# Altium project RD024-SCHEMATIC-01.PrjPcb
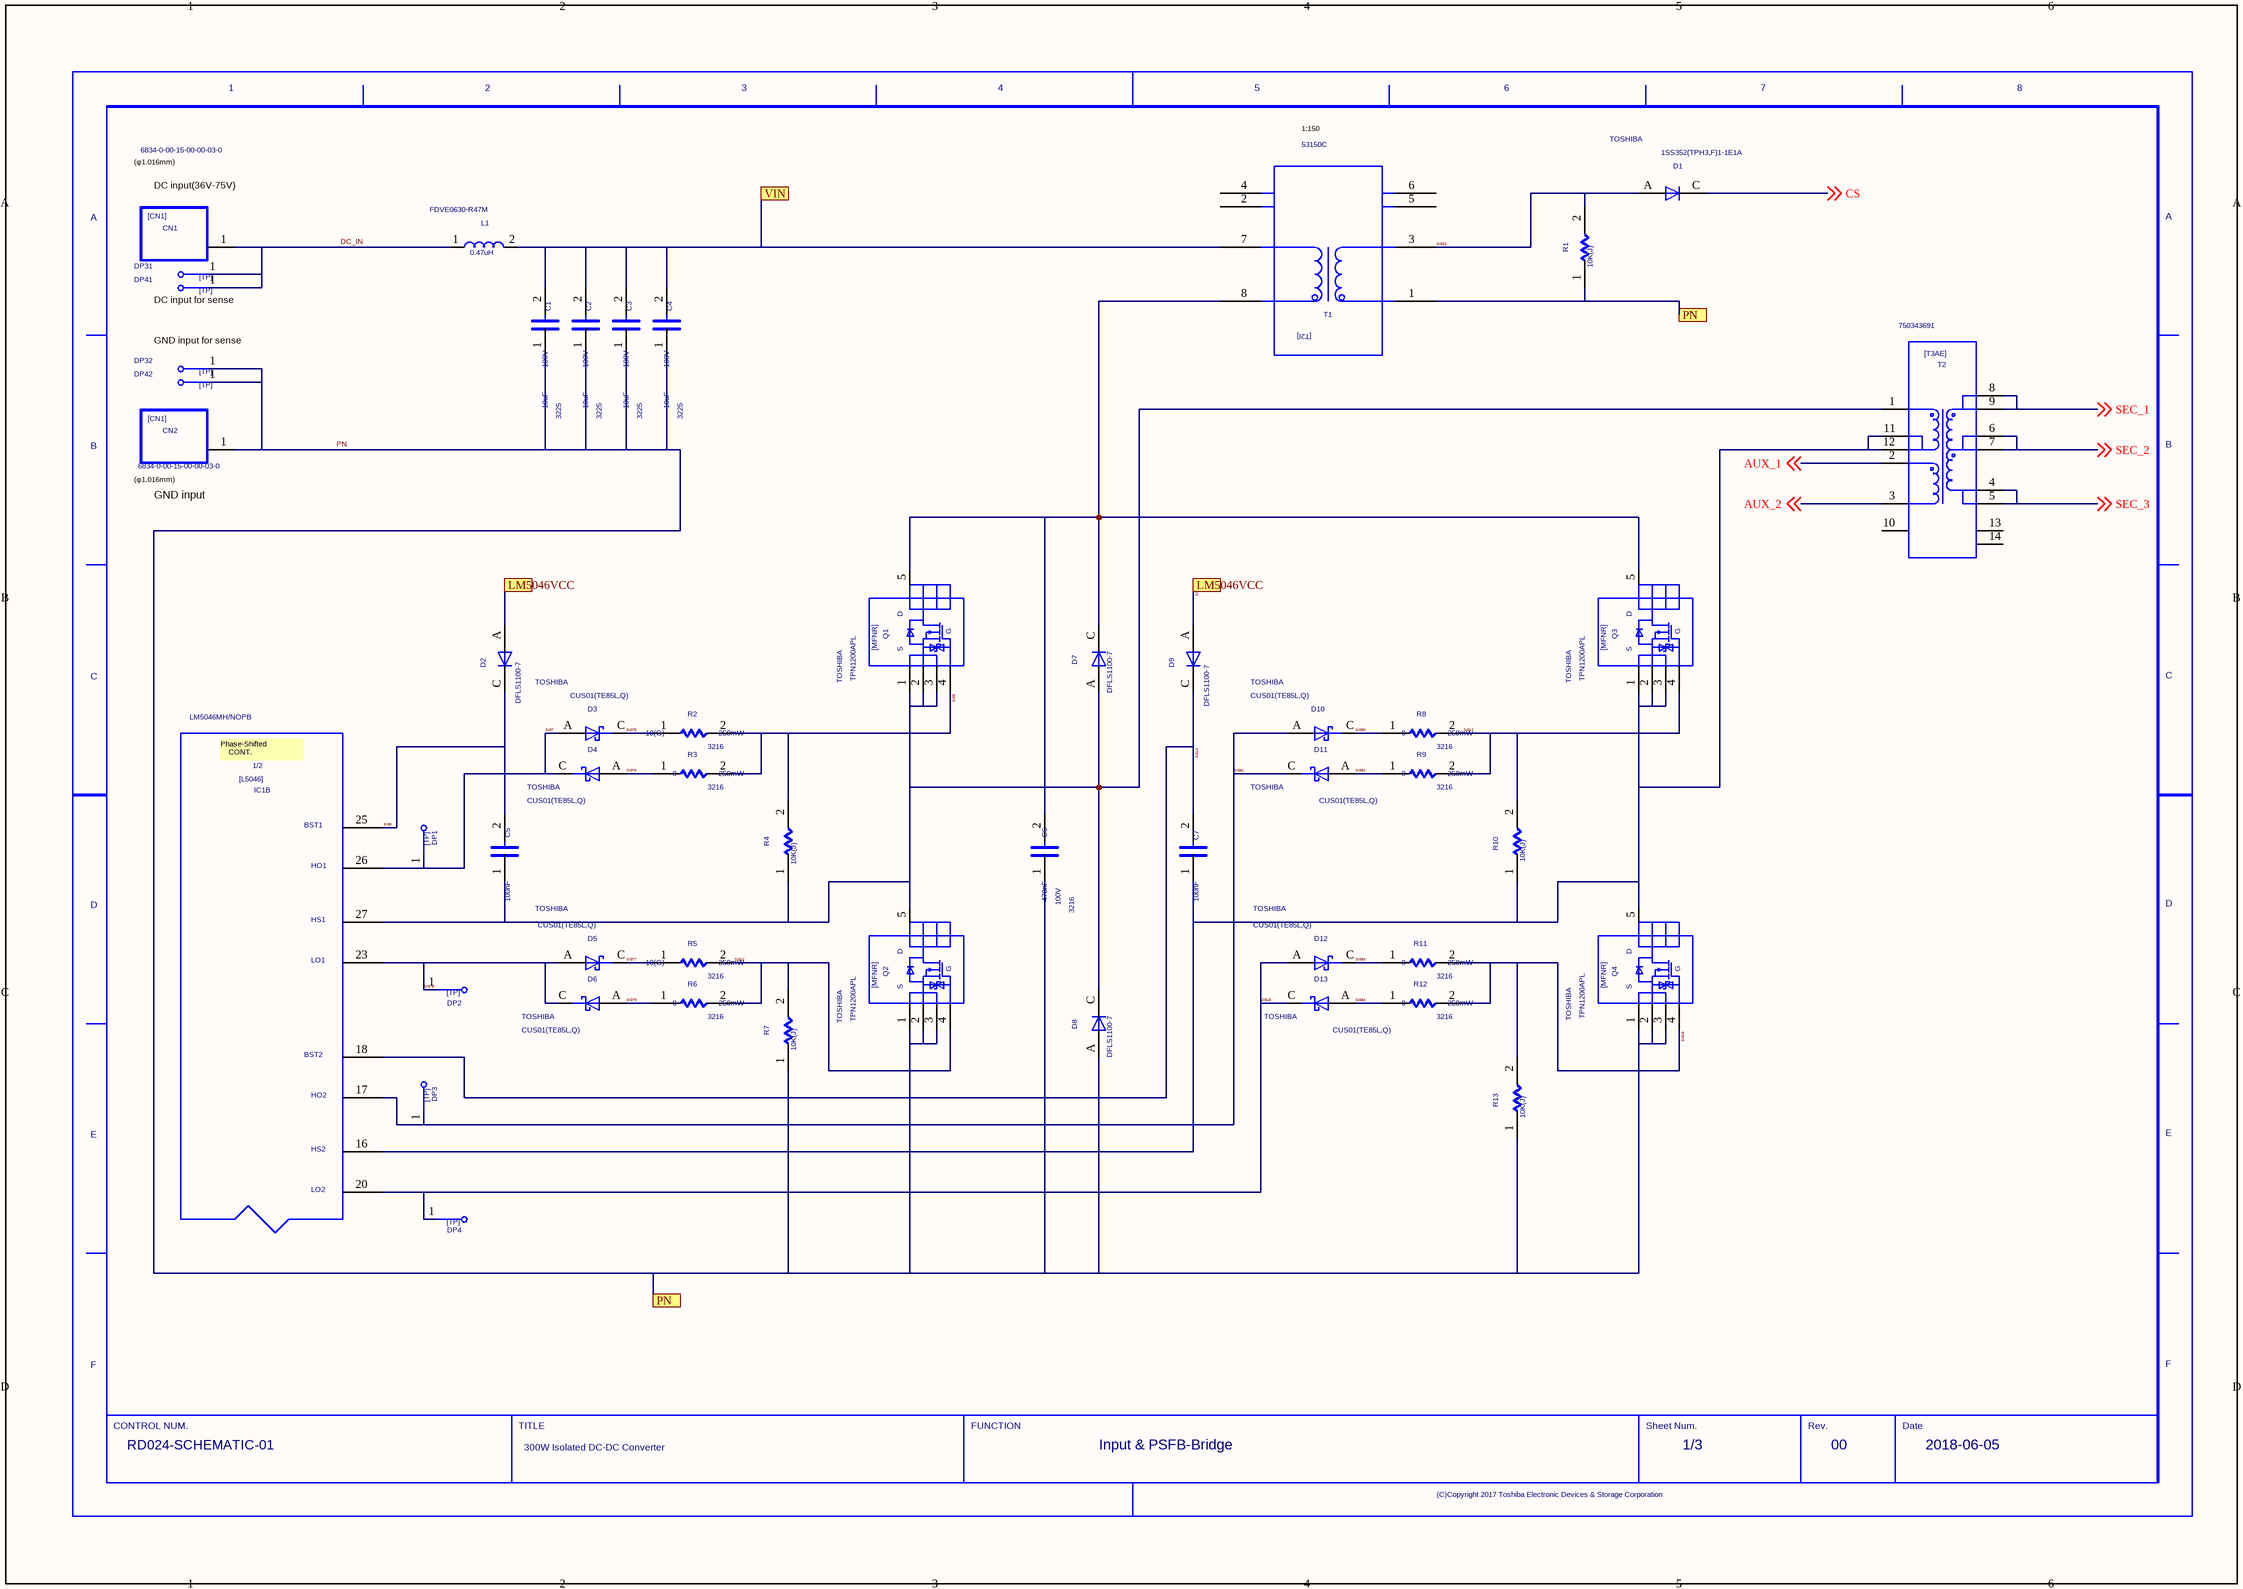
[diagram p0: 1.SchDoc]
3 sheets, 229 parts. Net scope: flat (ports and power ports of the same name join across sheets).
Sheets:
  1.SchDoc
  2.SchDoc
  3.SchDoc

## Sheet 1.SchDoc
size 420 x 297 mm

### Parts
(Parts that share a designator on the sheet are numbered #1, #2 ... from top to bottom, then left to right.)
C1  10uF  VALUE2: 100V  SIZECODESMD: 3225
C2  10uF  VALUE2: 100V  SIZECODESMD: 3225
C3  10uF  VALUE2: 100V  SIZECODESMD: 3225
C4  10uF  VALUE2: 100V  SIZECODESMD: 3225
C5  100nF
C6  470nF  VALUE2: 100V  COMPCOMMENT: 3216
C7  100nF
CN1  VALUE3: 6834-0-00-15-00-00-03-0  (hidden comment: CN1)
CN2  VALUE3: 6834-0-00-15-00-00-03-0  (hidden comment: CN1)
D1  1SS352(TPH3,F)1-1E1A  USERCOMPTEXT3: TOSHIBA
D2  VALUE3: DFLS1100-7  (hidden comment: D)
D3  CUS01(TE85L,Q)  USERCOMPTEXT3: TOSHIBA
D4  USERCOMPTEXT3: TOSHIBA  (hidden comment: CUS01(TE85L,Q))
D5  USERCOMPTEXT3: TOSHIBA  (hidden comment: CUS01(TE85L,Q))
D6  USERCOMPTEXT3: TOSHIBA  (hidden comment: CUS01(TE85L,Q))
D7  VALUE3: DFLS1100-7  (hidden comment: D)
D8  VALUE3: DFLS1100-7  (hidden comment: D)
D9  VALUE3: DFLS1100-7  (hidden comment: D)
D10  USERCOMPTEXT3: TOSHIBA  (hidden comment: CUS01(TE85L,Q))
D11  USERCOMPTEXT3: TOSHIBA  (hidden comment: CUS01(TE85L,Q))
D12  USERCOMPTEXT3: TOSHIBA  (hidden comment: CUS01(TE85L,Q))
D13  USERCOMPTEXT3: TOSHIBA  (hidden comment: CUS01(TE85L,Q))
DP1  TP  (value not drawn)
DP2  TP  (value not drawn)
DP3  TP  (value not drawn)
DP4  TP  (value not drawn)
DP31  TP  (value not drawn)
DP32  TP  (value not drawn)
DP41  TP  (value not drawn)
DP42  TP  (value not drawn)
IC1  VALUE3: LM5046MH/NOPB  (hidden comment: L5046_1)  (part B of 2)
L1  0.47uH  VALUE3: FDVE0630-R47M
Q1  USERCOMPTEXT3: TOSHIBA  VALUE3: TPN1200APL  (hidden comment: MFNR)
Q2  USERCOMPTEXT3: TOSHIBA  VALUE3: TPN1200APL  (hidden comment: MFNR)
Q3  USERCOMPTEXT3: TOSHIBA  VALUE3: TPN1200APL  (hidden comment: MFNR)
Q4  USERCOMPTEXT3: TOSHIBA  VALUE3: TPN1200APL  (hidden comment: MFNR)
R1  10K(J)
R2  10(G)  SIZECODESMD: 3216  VALUE2: 250mW
R3  0  VALUE2: 250mW  COMPCOMMENT: 3216
R4  10K(J)
R5  10(G)  SIZECODESMD: 3216  VALUE2: 250mW
R6  0  VALUE2: 250mW  COMPCOMMENT: 3216
R7  10K(J)
R8  0  VALUE2: 250mW  COMPCOMMENT: 3216
R9  0  VALUE2: 250mW  COMPCOMMENT: 3216
R10  10K(J)
R11  0  VALUE2: 250mW  COMPCOMMENT: 3216
R12  0  VALUE2: 250mW  COMPCOMMENT: 3216
R13  10K(J)
T1  VALUE3: 53150C  (hidden comment: T2I)
T2  VALUE3: 750343691  (hidden comment: T3AE)
U?#1  DATE: 2018-06-05  FUNCTION: Input & PSFB-Bridge  DRAWINGNUMBER: RD024-SCHEMATIC-01  TITLE: 300W Isolated DC-DC Converter  REVISION: 00  SHEETNUMBER: 1/3  (hidden comment: WAKU_DEF100)

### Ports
LM5046VCC, PN, VIN

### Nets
AUX_1: T2.2 ; off-sheet AUX_1
AUX_2: T2.3 ; off-sheet AUX_2
CS: D1.C ; off-sheet CS
DC_IN: CN1.1 DP31.1 DP41.1 L1.1
PN: C1.1 C2.1 C3.1 C4.1 C6.1 CN2.1 D8.A DP32.1 DP42.1 Q2.1 Q2.2 Q2.3 Q4.1 Q4.2 Q4.3 R1.1 R7.1 R13.1 T1.1 ; port PN
SEC_1: T2.8 T2.9 ; off-sheet SEC_1
SEC_2: T2.6 T2.7 ; off-sheet SEC_2
SEC_3: T2.4 T2.5 ; off-sheet SEC_3
SIG7: D3.A D4.C DP1.1 IC1.26
SIG8: C5.2 D2.C IC1.25
SIG9: Q1.4 R2.2 R3.2 R4.2
SIG12: Q2.4 R5.2 R6.2 R7.2
SIG13: D2.A D9.A ; port LM5046VCC
SIG14: C7.2 D9.C IC1.18
SIG16: Q4.4 R11.2 R12.2 R13.2
SIG17: Q3.4 R8.2 R9.2 R10.2
SIG18: D12.A D13.C DP4.1 IC1.20
SIG22: C6.2 D7.C Q1.5 Q3.5 T1.8
SIG23: D1.A R1.2 T1.3
SIG75: D3.C R2.1
SIG76: D4.A R3.1
SIG77: D5.C R5.1
SIG78: D5.A D6.C DP2.1 IC1.23
SIG79: D6.A R6.1
SIG80: D10.C R8.1
SIG81: D10.A D11.C DP3.1 IC1.17
SIG82: D11.A R9.1
SIG83: D12.C R11.1
SIG84: D13.A R12.1
SIG145: C5.1 D7.A D8.C IC1.27 Q1.1 Q1.2 Q1.3 Q2.5 R4.1 T2.1
SIG148: C7.1 IC1.16 Q3.1 Q3.2 Q3.3 Q4.5 R10.1 T2.11 T2.12
NetC1_2: C1.2 C2.2 C3.2 C4.2 L1.2 T1.7 ; port VIN

Not connected (* = marked no-connect by the designer): T1 2 4 5 6; T2 10 13 14

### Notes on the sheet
- (φ1.016mm)
- DC input(36V-75V)
- 1:150
- (near DP41) DC input for sense
- GND input for sense
- (near CN2) (φ1.016mm)
- (near CN2) GND input

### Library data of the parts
C1-C4 = C: SQ_PART_MODEL: CON_100U; OriginalSymbolOrigin: (2540,7620); RATEDVOLTAGE: 4; MAXGCOUNT: 1; OUMEMAKER: MRT 村田製作所; OUMECLASSIFICATION: セラミックコンデンサ; COMP: PRT_2; NOMINALCAPACITA: 100u; ADSCNVFLAG: ON; OUMEMAKERKATAMEI: GRM32EC80G107ME20L; ADSCOMPONENTNAME: C_3225; VALUE3: GRM32EC72A106KE05#; CAPACITANCETOLE: M; CDMASTERCADCELG: DC903A; ADSMODELNAME: s_GRM32EC80G107ME20L
C5 C7 = C: SQ_PART_MODEL: CON_100N; OriginalSymbolOrigin: (2540,7620); RATEDVOLTAGE: 25; MAXGCOUNT: 1; OUMEMAKER: MRT 村田製作所; OUMECLASSIFICATION: セラミックコンデンサ; COMP: PRT_4; SIZECODESMD: 1005; NOMINALCAPACITA: 100n; ADSCNVFLAG: ON; OUMEMAKERKATAMEI: GRM155R71E104KE14D; ADSCOMPONENTNAME: C_1005; VALUE3: GRM155R71E104KE14#; VALUE2: 25V; CAPACITANCETOLE: K; CDMASTERCADCELG: KC0005; ADSMODELNAME: s_GRM155R71E104KE14D
C6 = C: OriginalSymbolOrigin: (2540,7620); VALUE3: GRM31MR72A474KA35#; COMP: PRT_13
CN1 CN2 = CN1: OriginalSymbolOrigin: (2540,12700); COMP: PRT_16
D1 = D: SAVEAREA0: -225,-91,12804,7836; SAVECOUNT: 3; TIME: 14:49:55; UPDATEUSER: 19870035; UPDATETIME: 14:20:16; OriginalSymbolOrigin: (5080,5080); MAXGCOUNT: 1; COMP: PRT_3
D2 D7-D9 = D: SAVEAREA0: -225,-91,12804,7836; SAVECOUNT: 3; TIME: 14:49:55; UPDATEUSER: 19870035; UPDATETIME: 14:20:16; OriginalSymbolOrigin: (5080,5080); COMP: PRT_9
D3-D6 D10-D13 = SBD: OUMEPARTTYPE: D; SAVEAREA0: -4630,-153,17114,13055; TIME: 14:49:55; UPDATEUSER: fukuda-y; UPDATETIME: 08:16:22; SAVECOUNT: 9; OriginalSymbolOrigin: (5080,5080); MAXGCOUNT: 1; COMP: PRT_7
DP1-DP4 DP31 DP32 DP41 DP42 = TP: TIME: 16:12:21; UPDATEUSER: fukuda-y; UPDATETIME: 16:18:11; SAVECOUNT: 2; SAVEAREA0: -242,-92,12810,7836; OriginalSymbolOrigin: (0,7620); MAXGCOUNT: 1; COMP: PRT_10
IC1 = L5046_1: SAVEAREA0: -71804,-1007,117827,97484; TIME: 14:38:41; UPDATEUSER: cae; UPDATETIME: 09:49:47; SAVECOUNT: 16; OriginalSymbolOrigin: (7620,93980); CaptureCellPackProp: L5046_1B; COMP: PRT_6
L1 = L: OriginalSymbolOrigin: (2540,5080); RATEDCURRENT: 3.3; INDUCTANCEMAX: 0; MAXGCOUNT: 1; OUMEMAKER: TKO 東光; MOUNTINGFORMSMD: SMD; OUMECLASSIFICATION: 表面実装用固定コイル; COMP: PRT_1; ADSCNVFLAG: ON; OUMEMAKERKATAMEI: FDV0630-4R7M=P3; ADSCOMPONENTNAME: L_SMD; CDMASTERCADCELG: KD0074; ADSMODELNAME: s_FDV0630_4R7M_P3; NOMINALINDUCTA2: M; NOMINALINDUCTA1: 4.7u
Q1-Q4 = MFNR: SAVEAREA0: -11373,-4619,33654,28142; TIME: 18:57:44; UPDATEUSER: ikeda-k; UPDATETIME: 16:18:19; SAVECOUNT: 11; OriginalSymbolOrigin: (5080,20320); COMP: PRT_15
R1 = R: OriginalSymbolOrigin: (5080,5080); VALUE2: 63mW; MAXGCOUNT: 1; COMP: PRT_8; SIZECODESMD: 1005; VALUE3: ERJ2GEJ103X
R2 R5 = R: OriginalSymbolOrigin: (5080,5080); MAXGCOUNT: 1; VALUE3: RK73B2BTTD100G; COMP: PRT_14
R3 R6 R8 R9 R11 R12 = R: OriginalSymbolOrigin: (5080,5080); VALUE3: RK73Z2BRTTD; COMP: PRT_12
R4 R7 R10 R13 = R: OriginalSymbolOrigin: (5080,5080); MAXGCOUNT: 1; COMP: PRT_8; SIZECODESMD: 1005; VALUE3: ERJ2GEJ103X; VALUE2: 63mW
T1 = T2I: SAVEAREA0: -21366,-459,62077,41078; SAVECOUNT: 8; TIME: 14:27:07; UPDATEUSER: 19990028; UPDATETIME: 13:00:08; OriginalSymbolOrigin: (7620,38100); COMP: PRT_11
T2 = T3AE: SAVEAREA0: -34674,-485,56770,47009; TIME: 17:49:49; UPDATEUSER: cae; UPDATETIME: 15:15:30; SAVECOUNT: 3; OriginalSymbolOrigin: (5080,43180); COMP: PRT_17
U?#1 = WAKU_DEF100: PLOTTIME: HH:MM; SAVEAREA0: -45080,-4508,463680,304612; TIME: 09:33:31; UPDATEUSER: d5009410; UPDATETIME: 14:09:13; SAVECOUNT: 3; OriginalSymbolOrigin: (10160,284480); PAGENUMBER: 01; DESIGNED: TOSHIBA

## Sheet 2.SchDoc
size 420 x 297 mm
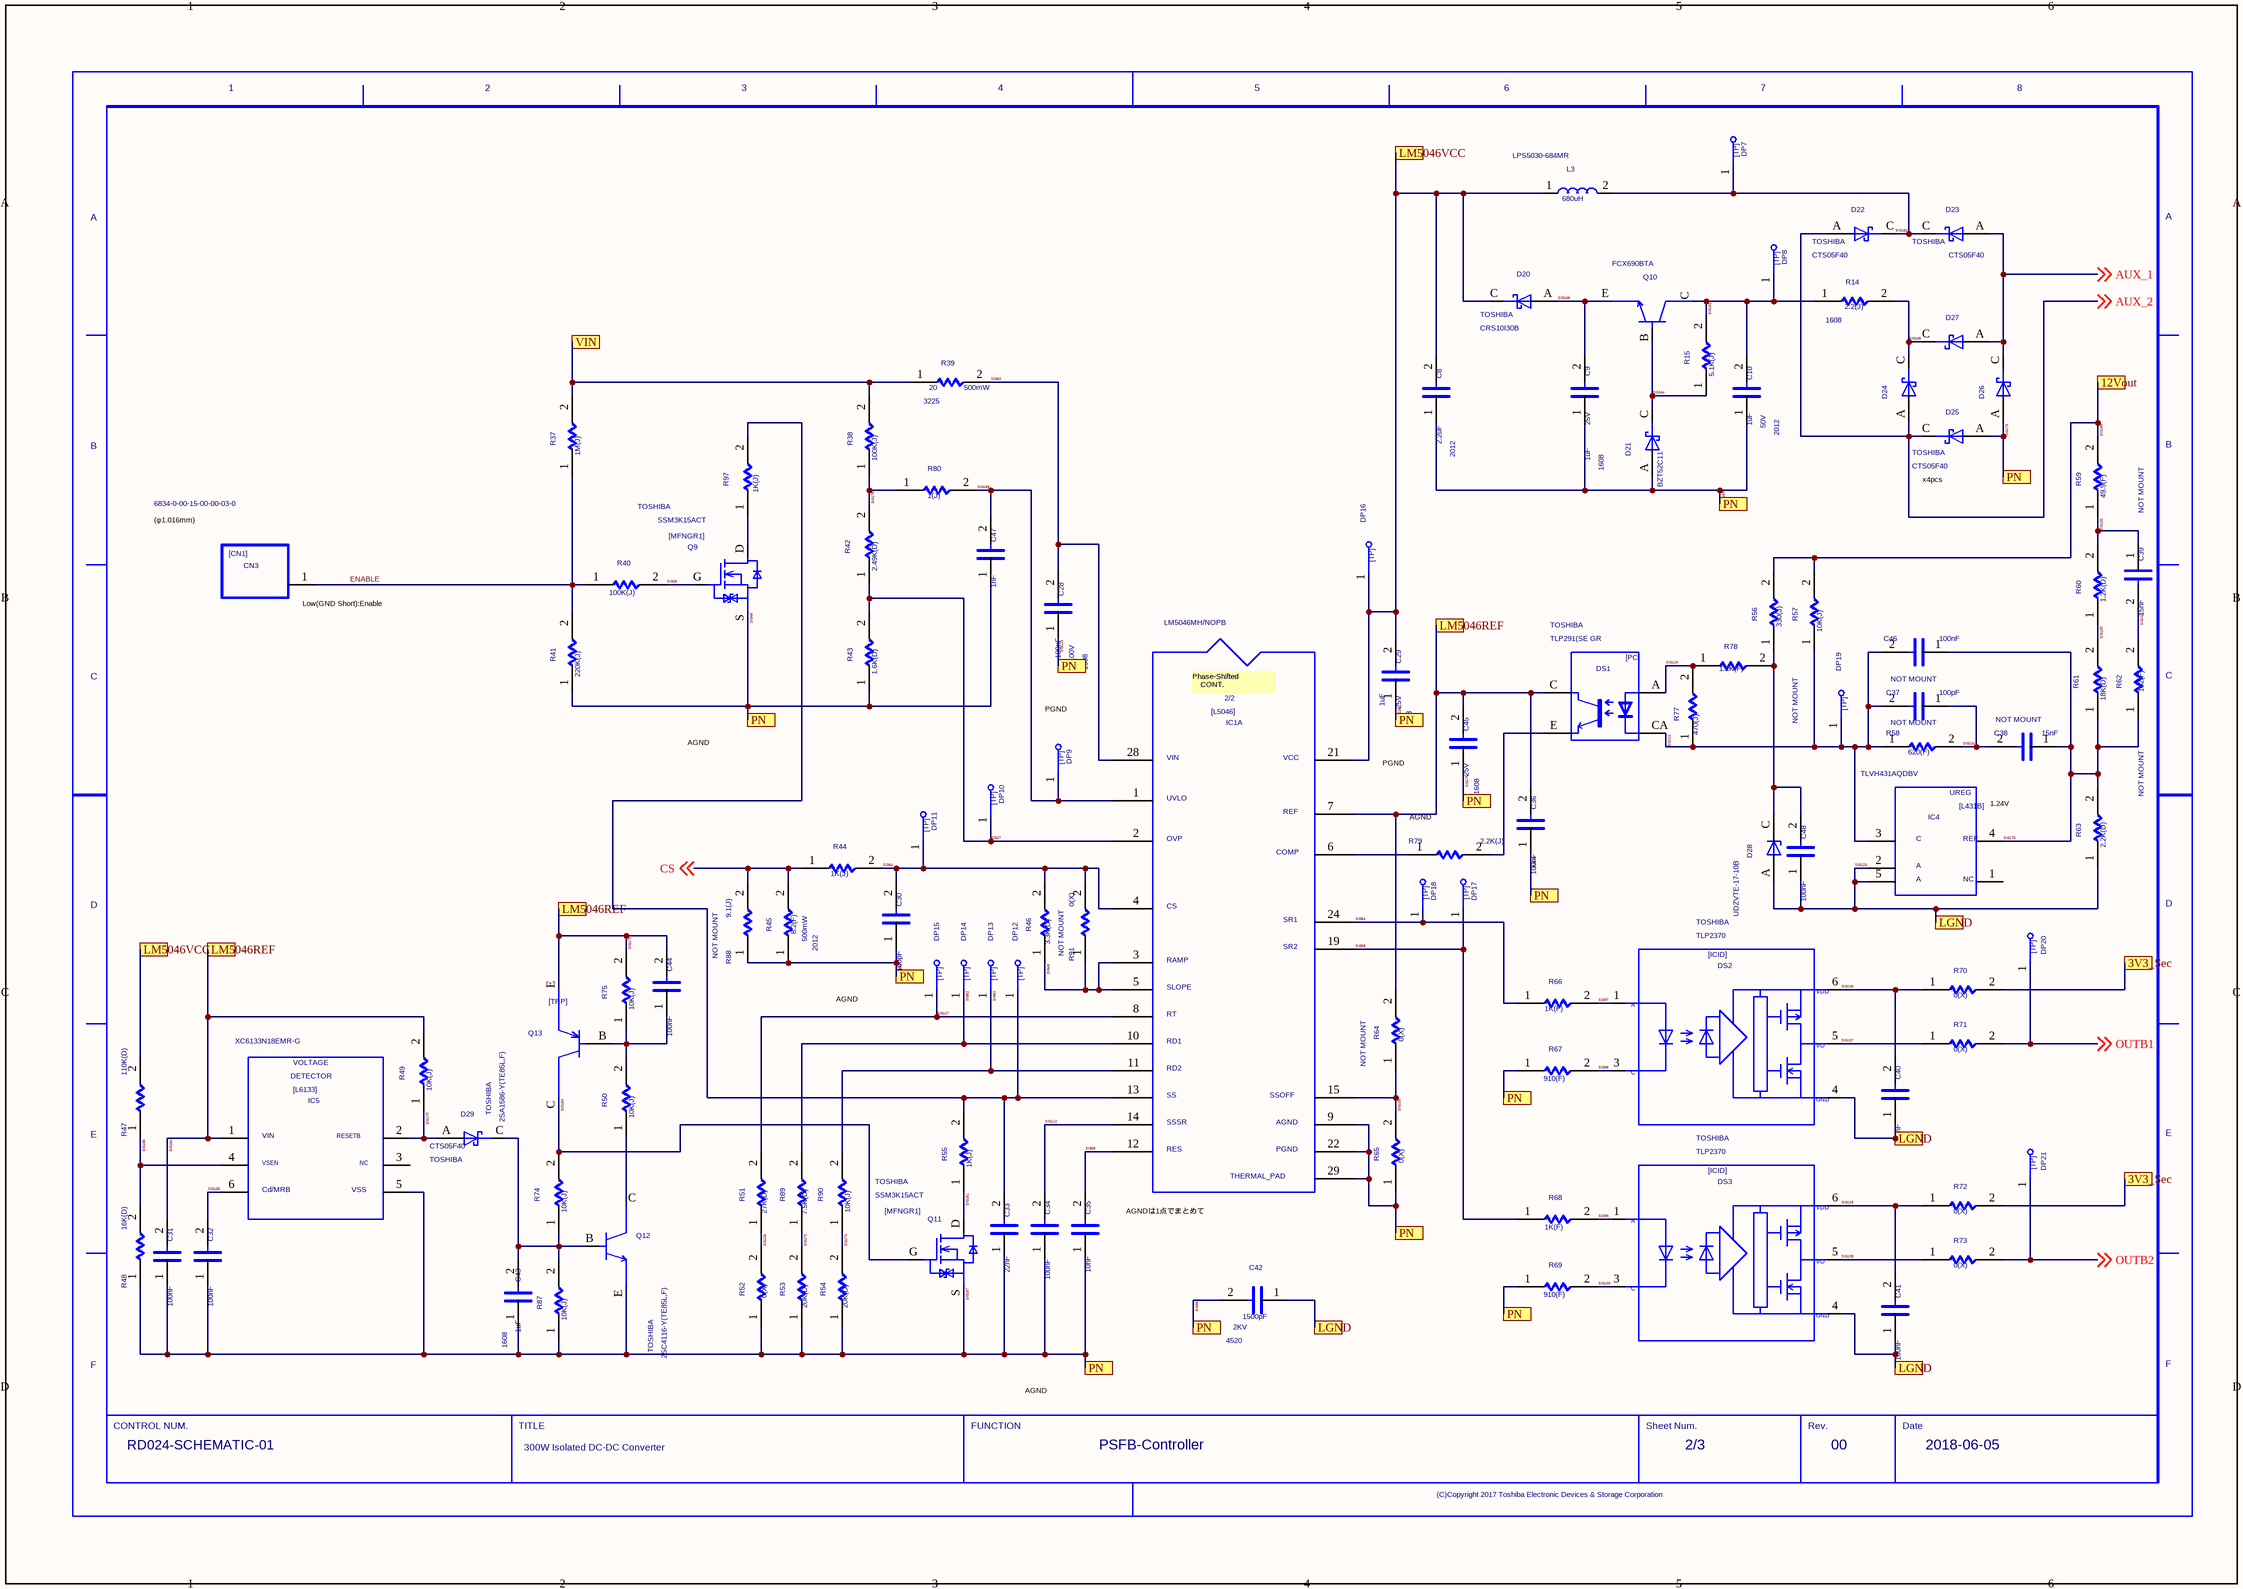
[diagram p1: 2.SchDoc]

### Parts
(Parts that share a designator on the sheet are numbered #1, #2 ... from top to bottom, then left to right.)
C8  2.2uF  SIZECODESMD: 2012
C9  1uF  SIZECODESMD: 1608  VALUE2: 25V
C10  1uF  SIZECODESMD: 2012  VALUE2: 50V
C28  100nF  SIZECODESMD: 1608  VALUE2: 100V
C29  1uF  SIZECODESMD: 1608  VALUE2: 25V
C30  100pF
C31  100nF
C32  100nF
C33  22nF
C34  100nF
C35  10nF
C36  100nF
C37  100pF  NOTMOUNT: NOT MOUNT
C38  15nF  NOTMOUNT: NOT MOUNT
C39  15nF  NOTMOUNT: NOT MOUNT
C40  100nF
C41  100nF
C42  1500pF  SIZECODESMD: 4520  VALUE2: 2KV
C43  1uF  COMPCOMMENT: 1608
C44  100nF
C45  1uF  SIZECODESMD: 1608  VALUE2: 25V
C46  100nF
C47  1nF
C48  100nF
CN3  VALUE3: 6834-0-00-15-00-00-03-0  (hidden comment: CN1)
D20  USERCOMPTEXT3: TOSHIBA  VALUE3: CRS10I30B  (hidden comment: SBD)
D21  VALUE3: BZT52C11  (hidden comment: SBD)
D22  USERCOMPTEXT3: TOSHIBA  VALUE3: CTS05F40  (hidden comment: SBD)
D23  USERCOMPTEXT3: TOSHIBA  VALUE3: CTS05F40  (hidden comment: SBD)
D24  SBD  (value not drawn)
D25  USERCOMPTEXT3: TOSHIBA  VALUE3: CTS05F40  (hidden comment: SBD)
D26  SBD  (value not drawn)
D27  SBD  (value not drawn)
D28  VALUE3: UDZVTE-17-10B  (hidden comment: ZD)
D29  USERCOMPTEXT3: TOSHIBA  VALUE3: CTS05F40  (hidden comment: SBD)
DP7  TP  (value not drawn)
DP8  TP  (value not drawn)
DP9  TP  (value not drawn)
DP10  TP  (value not drawn)
DP11  TP  (value not drawn)
DP12  TP  (value not drawn)
DP13  TP  (value not drawn)
DP14  TP  (value not drawn)
DP15  TP  (value not drawn)
DP16  TP  (value not drawn)
DP17  TP  (value not drawn)
DP18  TP  (value not drawn)
DP19  TP  (value not drawn)
DP20  TP  (value not drawn)
DP21  TP  (value not drawn)
DS1  USERCOMPTEXT3: TOSHIBA  VALUE3: TLP291(SE GR  (hidden comment: PC)
DS2  USERCOMPTEXT3: TOSHIBA  VALUE3: TLP2370  (hidden comment: ICID)
DS3  USERCOMPTEXT3: TOSHIBA  VALUE3: TLP2370  (hidden comment: ICID)
IC1  VALUE3: LM5046MH/NOPB  (hidden comment: L5046_1)  (part A of 2)
IC4  VALUE3: TLVH431AQDBV  (hidden comment: L431B)
IC5  VALUE3: XC6133N18EMR-G  (hidden comment: L6133)
L3  680uH  VALUE3: LPS5030-684MR
Q9  SSM3K15ACT  USERCOMPTEXT3: TOSHIBA
Q10  VALUE3: FCX690BTA  (hidden comment: TRN)
Q11  USERCOMPTEXT3: TOSHIBA  (hidden comment: SSM3K15ACT)
Q12  USERCOMPTEXT3: TOSHIBA  (hidden comment: 2SC4116-Y(TE85L,F))
Q13  USERCOMPTEXT3: TOSHIBA  (hidden comment: 2SA1586-Y(TE85L,F))
R14  2.2(J)  SIZECODESMD: 1608
R15  5.1K(J)
R37  1M(J)
R38  100K(J)
R39  20  SIZECODESMD: 3225  VALUE2: 500mW
R40  100K(J)
R41  220K(J)
R42  2.49K(D)
R43  1.6K(D)
R44  1K(J)
R45  8.2(F)  COMPCOMMENT: 2012  VALUE2: 500mW
R46  3.3K(D)
R47  110K(D)
R48  16K(D)
R49  10K(J)
R50  10K(J)
R51  27K(D)
R52  0(X)
R53  20K(D)
R54  20K(D)
R55  1K(J)
R56  330(J)
R57  10K(J)  NOTMOUNT: NOT MOUNT
R58  620(F)  NOTMOUNT: NOT MOUNT
R59  49.9(F)
R60  1.2K(D)
R61  18K(D)
R62  182(F)  NOTMOUNT: NOT MOUNT
R63  2.2K(D)
R64  0(X)  NOTMOUNT: NOT MOUNT
R65  0(X)
R66  1K(F)
R67  910(F)
R68  1K(F)
R69  910(F)
R70  0(X)
R71  0(X)
R72  0(X)
R73  0(X)
R74  10K(J)
R75  10K(J)
R77  470(J)
R78  1.2K(F)
R79  2.2K(J)
R80  1(J)
R87  10K(J)
R88  9.1(J)  NOTMOUNT: NOT MOUNT
R89  7.5K(D)
R90  10K(J)
R91  0(X)  NOTMOUNT: NOT MOUNT
R97  1K(J)
U?#2  DATE: 2018-06-05  FUNCTION: PSFB-Controller  DRAWINGNUMBER: RD024-SCHEMATIC-01  TITLE: 300W Isolated DC-DC Converter  REVISION: 00  SHEETNUMBER: 2/3  (hidden comment: WAKU_DEF100)

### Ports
3V3_Sec, 12Vout, LGND, LM5046REF, LM5046VCC, PN, VIN

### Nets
$BN000001: Q9.D R97.1
$BN000002: C48.2 D28.C R56.1 R78.2
$BN000003: C44.1 Q13.B R50.2 R75.1
$BN000004: Q12.C R50.1
$BN000005: DS1.E R79.2
AUX_1: D23.A D26.C D27.A ; off-sheet AUX_1
AUX_2: D22.A D24.A D25.C ; off-sheet AUX_2
CS: R44.1 R45.2 R88.2 ; off-sheet CS
ENABLE: CN3.1 R37.1 R40.1 R41.2
OUTB1: DP20.1 R71.2 ; off-sheet OUTB1
OUTB2: DP21.1 R73.2 ; off-sheet OUTB2
SIG13: C8.2 C29.2 D20.C DP16.1 IC1.21 L3.1 R47.2 ; port LM5046VCC
SIG25: Q9.G R40.2
SIG27: DP10.1 IC1.2 R42.1 R43.2
SIG49: IC1.3 IC1.5 R46.1 R91.1
SIG52: DP14.1 IC1.10 R89.2
SIG53: DP13.1 IC1.11 R90.2
SIG54: DP18.1 IC1.24 R66.1
SIG55: DP17.1 IC1.19 R68.1
SIG63: C28.2 IC1.28 R39.2
SIG64: C30.2 DP11.1 IC1.4 R44.2 R46.2 R91.2
SIG66: C35.2 IC1.12
SIG67: C33.2 DP12.1 IC1.13 R55.2 R97.2
SIG74: IC1.6 R79.1
SIG97: DS2.1 R66.2
SIG98: DS2.3 R67.2
SIG99: DS3.1 R68.2
SIG100: DS3.3 R69.2
SIG105: C8.1 C9.1 C10.1 C28.1 C29.1 C30.1 C31.1 C32.1 C33.1 C34.1 C35.1 C36.1 C42.2 C43.1 C45.1 C47.1 D21.A D25.A D26.A IC1.9 IC1.22 IC1.29 IC5.5 Q9.S Q11.S Q12.E R41.1 R43.1 R45.1 R48.1 R52.1 R53.1 R54.1 R65.1 R67.1 R69.1 R87.1 R88.1 ; port PN  [also labelled SIG113, SIG128, SIG157, SIG163, SIG175, SIG179, SIG48, SIG65, SIG96]  [project net PN]
SIG106: C40.2 DS2.6 R70.1
SIG107: DS2.5 R71.1
SIG108: C41.2 DS3.6 R72.1
SIG109: DS3.5 R73.1
SIG112: C34.2 IC1.14
SIG122: C37.2 C46.2 DP19.1 DS1.CA IC4.3 R57.1 R58.1 R77.1
SIG123: C40.1 C41.1 C42.1 C48.1 D28.A DS2.4 DS3.4 IC4.2 IC4.5 R63.1 ; port LGND  [project net LGND]
SIG124: C37.1 C38.2 R58.2
SIG126: R51.1 R52.2
SIG127: DP15.1 IC1.8 R51.2
SIG129: DS1.A R77.2 R78.1
SIG130: R60.1 R61.2
SIG131: C39.2 R62.2
SIG132: C39.1 R59.1 R60.2
SIG133: IC1.15 R64.1 R65.2
SIG151: Q11.D R55.1
SIG153: Q11.G Q13.C R74.2
SIG154: C31.2 C36.2 C44.2 C45.2 DS1.C IC1.7 IC5.1 Q13.E R49.2 R64.2 R75.2 ; port LM5046REF  [also labelled SIG171]
SIG155: C32.2 IC5.6
SIG156: IC5.4 R47.1 R48.2
SIG158: C47.2 DP9.1 IC1.1 R80.2
SIG161: C10.2 DP8.1 Q10.C R14.1 R15.2
SIG162: D22.C D23.C DP7.1 L3.2
SIG164: D21.C Q10.B R15.1
SIG165: D24.C D27.C R14.2
SIG168: C9.2 D20.A Q10.E
SIG169: R56.2 R57.2 R59.2 ; port 12Vout
SIG170: D29.A IC5.2 R49.1
SIG172: C43.2 D29.C Q12.B R74.1 R87.2
SIG173: R53.2 R89.1
SIG174: R54.2 R90.1
SIG176: R38.1 R42.2 R80.1
SIG178: C38.1 C46.1 IC4.4 R61.1 R62.1 R63.2
NetC1_2: R37.2 R38.2 R39.1 ; port VIN
NetC13_2: R70.2 R72.2 ; port 3V3_Sec

Not connected (* = marked no-connect by the designer): IC4 1; IC5 3

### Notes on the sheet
- (φ1.016mm)
- (near D25) x4pcs
- (near CN3) Low(GND Short):Enable
  Open:Disable
- PGND
- AGND
- (near R79) AGND
- 1.24V
- AGNDは1点でまとめて
  IC直近でPGNDと接続する

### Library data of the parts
C8 = C: SQ_PART_MODEL: CON_2.2U; OriginalSymbolOrigin: (2540,7620); RATEDVOLTAGE: 25; MAXGCOUNT: 1; OUMEMAKER: MRT 村田製作所; OUMECLASSIFICATION: セラミックコンデンサ; COMP: PRT_39; NOMINALCAPACITA: 2.2u; ADSCNVFLAG: ON; OUMEMAKERKATAMEI: GRM21BR71E225KA73L@@; ADSCOMPONENTNAME: C_2012; VALUE3: GRM21BR71E225KE11#; VALUE2: 25V; CAPACITANCETOLE: K; ADSMODELNAME: s_GRM21BR71E225KA73L@@
C9 C29 C45 = C: SQ_PART_MODEL: CON_1U; OriginalSymbolOrigin: (2540,7620); RATEDVOLTAGE: 25; MAXGCOUNT: 1; TEMPCHARACTERI2: B; OUMEMAKER: MRT 村田製作所; OUMECLASSIFICATION: セラミックコンデンサ; COMP: PRT_34; NOMINALCAPACITA: 1u; ADSCNVFLAG: ON; OUMEMAKERKATAMEI: GRM188B31E105KA75D; ADSCOMPONENTNAME: C_1608; VALUE3: GRJ188R71E105KE11#; CAPACITANCETOLE: K; CDMASTERCADCELG: KC0008; ADSMODELNAME: s_GRM188B31E105KA75D
C10 = C: SQ_PART_MODEL: CON_1U; OriginalSymbolOrigin: (2540,7620); RATEDVOLTAGE: 50; MAXGCOUNT: 1; OUMEMAKER: MRT 村田製作所; OUMECLASSIFICATION: セラミックコンデンサ; COMP: PRT_33; NOMINALCAPACITA: 1u; ADSCNVFLAG: ON; OUMEMAKERKATAMEI: GCM21BR71H105KA01L@@; ADSCOMPONENTNAME: C_2012; VALUE3: GRJ21BR71H105KE01#; CAPACITANCETOLE: K; CDMASTERCADCELG: KC0136; ADSMODELNAME: s_GCM21BR71H105KA01L@@
C28 = C: SQ_PART_MODEL: CON_100N; OriginalSymbolOrigin: (2540,7620); RATEDVOLTAGE: 100; MAXGCOUNT: 1; OUMEMAKER: MRT 村田製作所; OUMECLASSIFICATION: セラミックコンデンサ; COMP: PRT_51; NOMINALCAPACITA: 100n; ADSCNVFLAG: ON; OUMEMAKERKATAMEI: GRM188R72A104KA35D; ADSCOMPONENTNAME: C_1608; VALUE3: GRM188R72A104KA35#; CAPACITANCETOLE: K; CDMASTERCADCELG: KC0008; ADSMODELNAME: s_GRM188R72A104KA35D
C30 C37 = C: SQ_PART_MODEL: CON_100P; OriginalSymbolOrigin: (2540,7620); RATEDVOLTAGE: 50; MAXGCOUNT: 1; OUMEMAKER: MRT 村田製作所; OUMECLASSIFICATION: セラミックコンデンサ; COMP: PRT_55; SIZECODESMD: 1005; NOMINALCAPACITA: 100p; ADSCNVFLAG: ON; OUMEMAKERKATAMEI: GRM1555C1H101JA01D; ADSCOMPONENTNAME: C_1005; VALUE3: GRM1555C1H101JA01#; VALUE2: 50V; CAPACITANCETOLE: J; CDMASTERCADCELG: KC0005; ADSMODELNAME: s_GRM1555C1H101JA01D
C31 C32 C34 C36 C40 C41 C44 C46 C48 = C: as C5 on sheet 1
C33 = C: SQ_PART_MODEL: CON_22N; OriginalSymbolOrigin: (2540,7620); RATEDVOLTAGE: 25; MAXGCOUNT: 1; OUMEMAKER: MRT 村田製作所; OUMECLASSIFICATION: セラミックコンデンサ; COMP: PRT_20; SIZECODESMD: 1005; NOMINALCAPACITA: 22n; ADSCNVFLAG: ON; OUMEMAKERKATAMEI: GRM155R71E223KA61D; ADSCOMPONENTNAME: C_1005; VALUE3: GRM155R71E223KA61#; VALUE2: 25V; CAPACITANCETOLE: K; CDMASTERCADCELG: KC0005; ADSMODELNAME: s_GRM155R71E223KA61D
C35 = C: SQ_PART_MODEL: CON_10N; OriginalSymbolOrigin: (2540,7620); RATEDVOLTAGE: 25; MAXGCOUNT: 1; OUMEMAKER: MRT 村田製作所; OUMECLASSIFICATION: セラミックコンデンサ; COMP: PRT_19; SIZECODESMD: 1005; NOMINALCAPACITA: 10n; ADSCNVFLAG: ON; OUMEMAKERKATAMEI: GRM155R71E103KA01D; ADSCOMPONENTNAME: C_1005; VALUE3: GRM155R71E103KA01#; VALUE2: 25V; CAPACITANCETOLE: K; CDMASTERCADCELG: KC0005; ADSMODELNAME: s_GRM155R71E103KA01D
C38 C39 = C: SQ_PART_MODEL: CON_15N; OriginalSymbolOrigin: (2540,7620); RATEDVOLTAGE: 50; MAXGCOUNT: 1; TEMPCHARACTERI2: B; OUMEMAKER: TDK ＴＤＫ; OUMECLASSIFICATION: セラミックコンデンサ; COMP: PRT_23; SIZECODESMD: 1005; NOMINALCAPACITA: 15n; ADSCNVFLAG: ON; OUMEMAKERKATAMEI: C1005JB1H153KT; ADSCOMPONENTNAME: C_1005; VALUE3: GRM155R71E153KA61#; VALUE2: 25V; CAPACITANCETOLE: K; CDMASTERCADCELG: KC0005; ADSMODELNAME: s_C1005JB1H153KT
C42 = C: SQ_PART_MODEL: CON_1N; OriginalSymbolOrigin: (2540,7620); RATEDVOLTAGE: 2K; MAXGCOUNT: 1; OUMEMAKER: MRT 村田製作所; OUMECLASSIFICATION: セラミックコンデンサ; COMP: PRT_22; NOMINALCAPACITA: 1n; ADSCNVFLAG: ON; OUMEMAKERKATAMEI: GR442QR73D102KW01L; ADSCOMPONENTNAME: C_4520; VALUE3: GR442QR73D152KW01-01; CAPACITANCETOLE: K; CDMASTERCADCELG: KC0071; ADSMODELNAME: s_GR442QR73D102KW01L
C43 = C: OriginalSymbolOrigin: (2540,7620); VALUE3: GRJ188R71E105KE11#; VALUE2: 25V; COMP: PRT_5
C47 = C: SQ_PART_MODEL: CON_1N; OriginalSymbolOrigin: (2540,7620); COMP: PRT_50; RATEDVOLTAGE: 50; MAXGCOUNT: 1; TEMPCHARACTERI2: CH; OUMEMAKER: MRT 村田製作所; OUMECLASSIFICATION: セラミックコンデンサ; SIZECODESMD: 1005; NOMINALCAPACITA: 1n; ADSCNVFLAG: ON; OUMEMAKERKATAMEI: GRM1552C1H102JA01D; ADSCOMPONENTNAME: C_1005; VALUE3: GRM155R71H102KA01#; VALUE2: 50V; CAPACITANCETOLE: J; CDMASTERCADCELG: KC0005; ADSMODELNAME: s_GRM1552C1H102JA01D
CN3 = CN1: as CN1 on sheet 1
D20 = SBD: OUMEPARTTYPE: D; SAVEAREA0: -225,-91,12804,7836; TIME: 14:49:55; UPDATEUSER: 19870035; UPDATETIME: 14:20:16; SAVECOUNT: 9; OriginalSymbolOrigin: (5080,5080); MAXGCOUNT: 1; MOUNTINGFORMSMD: SMD; PEAKFORWARDVOLT: 390m; MAXREPETITIVEPE: 30; FORWARDVOLTAGEM: 0; REVERSECURRENT: 60u; CDMASTERCADCELG: MMK0167; OUMEMAKER: TSB 東芝; OUMEMAKERKATAMEI: CRS10I30A; OUMECLASSIFICATION: 高速用整流素子/ショットキバリアダイオード; ADSMODELNAME: s_CRS10I30A; COMP: PRT_49
D21 = SBD: SAVEAREA0: -4630,-153,17114,13055; TIME: 14:49:55; UPDATEUSER: fukuda-y; UPDATETIME: 08:16:22; SAVECOUNT: 9; OriginalSymbolOrigin: (5080,5080); COMP: PRT_35
D22 D23 = SBD: OUMEPARTTYPE: D; SAVEAREA0: -4630,-153,17114,13055; TIME: 14:49:55; UPDATEUSER: fukuda-y; UPDATETIME: 08:16:22; SAVECOUNT: 9; OriginalSymbolOrigin: (5080,5080); FORWARDVOLTAGEM: 0; MAXGCOUNT: 1; MAXREPETITIVEPE: 30; OUMEMAKER: TSB 東芝; MAXAVERAGEFORWA: 500m; MOUNTINGFORMSMD: SMD; OUMECLASSIFICATION: 高速用整流素子/ショットキバリアダイオード; COMP: PRT_48; OUMEMAKERKATAMEI: CTS05S30; CDMASTERCADCELG: KCK0242; ADSMODELNAME: s_CTS05S30
D24 D26 D27 = SBD: SAVEAREA0: -4630,-153,17114,13055; TIME: 14:49:55; UPDATEUSER: fukuda-y; UPDATETIME: 08:16:22; SAVECOUNT: 9; OriginalSymbolOrigin: (5080,5080); USERCOMPTEXT3: TOSHIBA; VALUE3: CTS05F40; COMP: PRT_48
D25 D29 = SBD: SAVEAREA0: -4630,-153,17114,13055; TIME: 14:49:55; UPDATEUSER: fukuda-y; UPDATETIME: 08:16:22; SAVECOUNT: 9; OriginalSymbolOrigin: (5080,5080); COMP: PRT_48
D28 = ZD: SAVEAREA0: -4630,-153,17114,13055; TIME: 14:49:55; UPDATEUSER: fukuda-y; UPDATETIME: 08:18:42; SAVECOUNT: 6; OriginalSymbolOrigin: (5080,5080); COMP: PRT_63
DP7-DP21 = TP: as DP1 on sheet 1
DS1 = PC: OriginalSymbolOrigin: (5080,17780); COMP: PRT_21
DS2 DS3 = ICID: TIME: 11:37:10; UPDATEUSER: cae; UPDATETIME: 10:02:13; SAVECOUNT: 16; SAVEAREA0: -15781,-397,59072,38480; OriginalSymbolOrigin: (2540,35560); COMP: PRT_72
IC1 = L5046_1: SAVEAREA0: -71804,-1007,117827,97484; TIME: 14:38:41; UPDATEUSER: cae; UPDATETIME: 09:49:47; SAVECOUNT: 16; OriginalSymbolOrigin: (7620,93980); CaptureCellPackProp: L5046_1A; COMP: PRT_6
IC4 = L431B: SAVEAREA0: -12224,-318,37706,25614; TIME: 11:47:14; UPDATEUSER: cae; UPDATETIME: 15:43:57; SAVECOUNT: 6; OriginalSymbolOrigin: (5080,22860); COMP: PRT_56
IC5 = L6133: TIME: 13:21:52; UPDATEUSER: cae; UPDATETIME: 10:15:35; SAVECOUNT: 15; SAVEAREA0: -9663,-435,45411,35893; OriginalSymbolOrigin: (5080,33020); COMP: PRT_58
L3 = L: OriginalSymbolOrigin: (2540,5080); RATEDCURRENT: 4.3; INDUCTANCEMAX: 0; MAXGCOUNT: 1; OUMEMAKER: CCT コイルクラフト; MOUNTINGFORMSMD: SMD; OUMECLASSIFICATION: 表面実装用固定コイル; COMP: PRT_37; ADSCNVFLAG: ON; OUMEMAKERKATAMEI: XAL5030-472ME-HDD; ADSCOMPONENTNAME: L_SMD; CDMASTERCADCELG: KCK0316; ADSMODELNAME: s_XAL5030_472ME_HDD; NOMINALINDUCTA2: M; NOMINALINDUCTA1: 4.7u
Q9 Q11 = MFNGR1: OUMEPARTTYPE: Q; SAVECOUNT: 24; SAVEAREA0: -14204,-8572,26849,21288; TIME: 16:49:03; UPDATEUSER: ikeda-k; UPDATETIME: 18:49:38; OriginalSymbolOrigin: (2540,10160); MAXGCOUNT: 1; COMP: PRT_18
Q10 = TRN: TIME: 09:39:04; UPDATEUSER: 19910145; UPDATETIME: 15:12:10; SAVECOUNT: 8; SAVEAREA0: -6194,-158,18648,15662; OriginalSymbolOrigin: (2540,17780); COMP: PRT_36
Q12 = TRN: OUMEPARTTYPE: Q; TIME: 09:39:04; UPDATEUSER: 19910145; UPDATETIME: 15:12:10; SAVECOUNT: 8; SAVEAREA0: -6194,-158,18648,15662; OriginalSymbolOrigin: (2540,17780); MAXGCOUNT: 1; COMP: PRT_62
Q13 = TRP: OUMEPARTTYPE: Q; TIME: 09:39:04; UPDATEUSER: 19870035; UPDATETIME: 15:34:42; SAVECOUNT: 12; SAVEAREA0: -5466,-244,29263,20886; OriginalSymbolOrigin: (5080,22860); MAXGCOUNT: 1; COMP: PRT_61
R14 = R: OriginalSymbolOrigin: (5080,5080); MAXGCOUNT: 1; COMP: PRT_41; VALUE3: ERJ3GEYJ2R2V@@; VALUE2: 100mW
R15 = R: OriginalSymbolOrigin: (5080,5080); MAXGCOUNT: 1; COMP: PRT_40; SIZECODESMD: 1005; VALUE3: ERJ2GEJ512X; VALUE2: 63mW
R37 = R: OriginalSymbolOrigin: (5080,5080); MAXGCOUNT: 1; COMP: PRT_29; SIZECODESMD: 1005; VALUE3: ERJ2GEJ105X; VALUE2: 63mW
R38 R40 = R: OriginalSymbolOrigin: (5080,5080); MAXGCOUNT: 1; COMP: PRT_27; SIZECODESMD: 1005; VALUE3: ERJ2GEJ104X; VALUE2: 63mW
R39 = R: SQ_PART_MODEL: RES_20; OriginalSymbolOrigin: (5080,5080); MAXGCOUNT: 1; OUMEMAKER: NAE パナソニックエレクトロニックデバイス; MOUNTINGFORMSMD: SMD; OUMECLASSIFICATION: 表面実装用固定抵抗器; COMP: PRT_31; RESISTANCETOLER: J; ADSCNVFLAG: ON; POWERRATING: 250m; OUMEMAKERKATAMEI: ERJ14YJ200H; ADSCOMPONENTNAME: R_3225; VALUE3: ERJ14YJ200U; CDMASTERCADCELG: DR903A; ADSMODELNAME: s_ERJ14YJ200H
R41 = R: OriginalSymbolOrigin: (5080,5080); MAXGCOUNT: 1; COMP: PRT_26; SIZECODESMD: 1005; VALUE3: ERJ2GEJ224X; VALUE2: 63mW
R42 = R: OriginalSymbolOrigin: (5080,5080); MAXGCOUNT: 1; COMP: PRT_59; SIZECODESMD: 1005; VALUE3: ERJ2RHD2491X; VALUE2: 63mW
R43 = R: OriginalSymbolOrigin: (5080,5080); VALUE3: ERJ2RHD162X; MAXGCOUNT: 1; COMP: PRT_28; SIZECODESMD: 1005; VALUE2: 63mW
R44 R55 R97 = R: OriginalSymbolOrigin: (5080,5080); MAXGCOUNT: 1; COMP: PRT_30; SIZECODESMD: 1005; VALUE3: ERJ2GEJ102X; VALUE2: 63mW
R45 = R: OriginalSymbolOrigin: (5080,5080); COMP: PRT_57; VALUE3: ERJ6DQF8R2V
R46 = R: OriginalSymbolOrigin: (5080,5080); MAXGCOUNT: 1; COMP: PRT_66; SIZECODESMD: 1005; VALUE3: ERJ2RHD332X; VALUE2: 63mW
R47 = R: OriginalSymbolOrigin: (5080,5080); MAXGCOUNT: 1; COMP: PRT_53; SIZECODESMD: 1005; VALUE3: ERJ2RKD114X; VALUE2: 63mW
R48 = R: OriginalSymbolOrigin: (5080,5080); MAXGCOUNT: 1; COMP: PRT_54; SIZECODESMD: 1005; VALUE3: ERJ2RHD163X; VALUE2: 63mW
R49 R50 R57 R74 R75 R87 R90 = R: as R4 on sheet 1
R51 = R: OriginalSymbolOrigin: (5080,5080); MAXGCOUNT: 1; COMP: PRT_65; SIZECODESMD: 1005; VALUE3: ERJ2RHD273X; VALUE2: 63mW
R52 R64 R65 R70-R73 R91 = R: OriginalSymbolOrigin: (5080,5080); MAXGCOUNT: 1; COMP: PRT_25; SIZECODESMD: 1005; VALUE3: ERJ2GE0R00X; VALUE2: 63mW
R53 R54 = R: OriginalSymbolOrigin: (5080,5080); MAXGCOUNT: 1; COMP: PRT_52; SIZECODESMD: 1005; VALUE3: ERJ2RHD203X; VALUE2: 63mW
R56 = R: OriginalSymbolOrigin: (5080,5080); MAXGCOUNT: 1; COMP: PRT_71; SIZECODESMD: 1005; VALUE3: ERJ2GEJ331X; VALUE2: 63mW
R58 = R: OriginalSymbolOrigin: (5080,5080); MAXGCOUNT: 1; COMP: PRT_70; SIZECODESMD: 1005; VALUE3: ERJ2RKF6200X; VALUE2: 63mW
R59 = R: OriginalSymbolOrigin: (5080,5080); MAXGCOUNT: 1; COMP: PRT_24; SIZECODESMD: 1005; VALUE3: ERJ2RKF49R9X; VALUE2: 63mW
R60 = R: OriginalSymbolOrigin: (5080,5080); MAXGCOUNT: 1; COMP: PRT_42; SIZECODESMD: 1005; VALUE3: ERJ2RHD122X; VALUE2: 63mW; UPDATETIME: 18:40:58; UPDATEUSER: user1; TIME: 13:31:56; SAVEAREA0: -17703,-20267,33725,19386; MONOCODE: E00000333
R61 = R: OriginalSymbolOrigin: (5080,5080); MAXGCOUNT: 1; COMP: PRT_43; SIZECODESMD: 1005; VALUE3: ERJ2RHD183X; VALUE2: 63mW
R62 = R: OriginalSymbolOrigin: (5080,5080); MAXGCOUNT: 1; COMP: PRT_60; SIZECODESMD: 1005; VALUE3: RC0402FR-07182RL; VALUE2: 63mW
R63 = R: OriginalSymbolOrigin: (5080,5080); MAXGCOUNT: 1; COMP: PRT_44; SIZECODESMD: 1005; VALUE3: ERJ2RHD222X; VALUE2: 63mW
R66 R68 = R: OriginalSymbolOrigin: (5080,5080); MAXGCOUNT: 1; COMP: PRT_45; SIZECODESMD: 1005; VALUE3: ERJ2RKF1001X; VALUE2: 63mW
R67 R69 = R: OriginalSymbolOrigin: (5080,5080); MAXGCOUNT: 1; COMP: PRT_46; SIZECODESMD: 1005; VALUE3: RK73H1ETTP9100F; VALUE2: 63mW
R77 = R: OriginalSymbolOrigin: (5080,5080); MAXGCOUNT: 1; COMP: PRT_68; SIZECODESMD: 1005; VALUE3: ERJ2GEJ471X; VALUE2: 63mW
R78 = R: OriginalSymbolOrigin: (5080,5080); MAXGCOUNT: 1; COMP: PRT_69; SIZECODESMD: 1005; VALUE3: ERJ2RKF1201X; VALUE2: 63mW
R79 = R: OriginalSymbolOrigin: (5080,5080); MAXGCOUNT: 1; COMP: PRT_67; SIZECODESMD: 1005; VALUE3: ERJ2GEJ222X; VALUE2: 63mW
R80 = R: OriginalSymbolOrigin: (5080,5080); MAXGCOUNT: 1; COMP: PRT_32; SIZECODESMD: 1005; VALUE3: ERJ2GEJ1R0X; VALUE2: 63mW
R88 = R: OriginalSymbolOrigin: (5080,5080); MAXGCOUNT: 1; COMP: PRT_47; SIZECODESMD: 1005; VALUE3: ERJ2GEJ9R1X; VALUE2: 63mW
R89 = R: OriginalSymbolOrigin: (5080,5080); MAXGCOUNT: 1; COMP: PRT_64; SIZECODESMD: 1005; VALUE3: ERJ2RHD752X; VALUE2: 63mW
U?#2 = WAKU_DEF100: PLOTTIME: HH:MM; SAVEAREA0: -45080,-4508,463680,304612; TIME: 11:06:15; UPDATEUSER: d5009410; UPDATETIME: 14:09:25; SAVECOUNT: 3; OriginalSymbolOrigin: (10160,284480); PAGENUMBER: 03; DESIGNED: TOSHIBA

## Sheet 3.SchDoc
size 420 x 297 mm
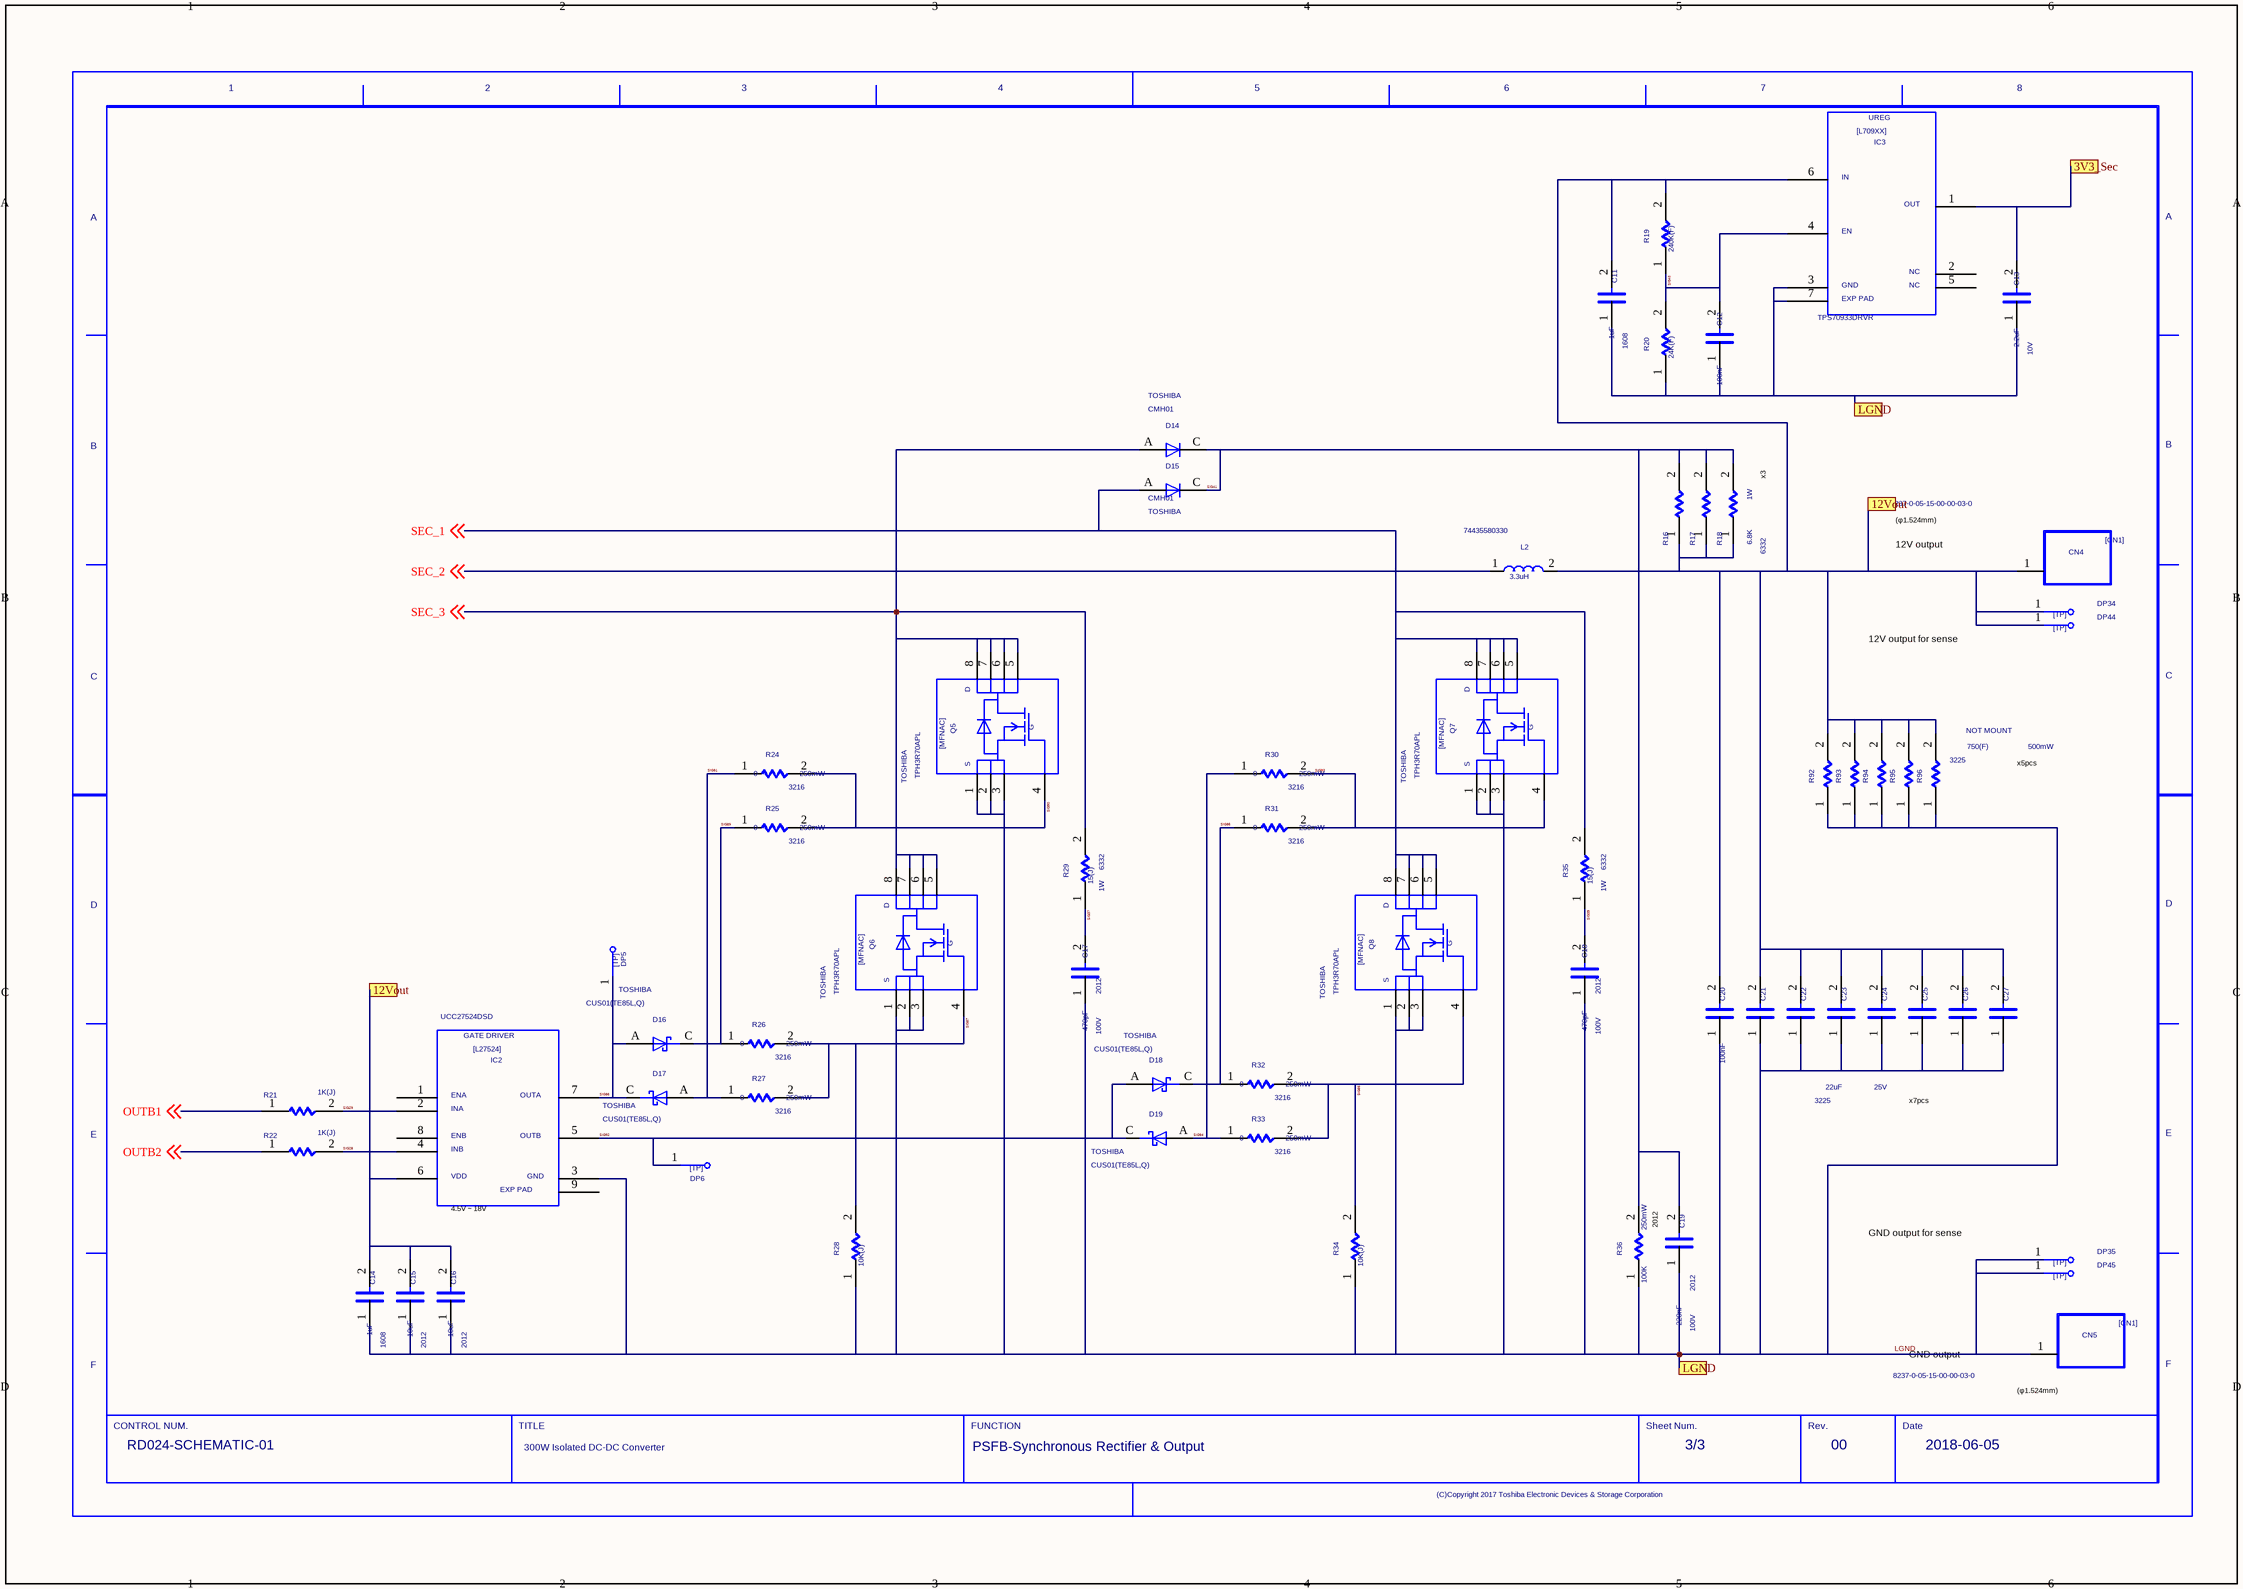
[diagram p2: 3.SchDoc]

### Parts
(Parts that share a designator on the sheet are numbered #1, #2 ... from top to bottom, then left to right.)
C11  1uF  SIZECODESMD: 1608
C12  100nF
C13  2.2uF  VALUE2: 10V
C14  1uF  SIZECODESMD: 1608
C15  10uF  SIZECODESMD: 2012
C16  10uF  SIZECODESMD: 2012
C17  470pF  VALUE2: 100V  COMPCOMMENT: 2012
C18  470pF  VALUE2: 100V  COMPCOMMENT: 2012
C19  220nF  SIZECODESMD: 2012  VALUE2: 100V
C20  100nF
C21  22uF  SIZECODESMD: 3225  VALUE2: 25V
C22  22uF  (value not drawn)
C23  22uF  (value not drawn)
C24  22uF  (value not drawn)
C25  22uF  (value not drawn)
C26  22uF  (value not drawn)
C27  22uF  (value not drawn)
CN4  VALUE3: 8237-0-05-15-00-00-03-0  (hidden comment: CN1)
CN5  VALUE3: 8237-0-05-15-00-00-03-0  (hidden comment: CN1)
D14  USERCOMPTEXT3: TOSHIBA  VALUE3: CMH01  (hidden comment: D)
D15  USERCOMPTEXT3: TOSHIBA  VALUE3: CMH01  (hidden comment: D)
D16  USERCOMPTEXT3: TOSHIBA  (hidden comment: CUS01(TE85L,Q))
D17  USERCOMPTEXT3: TOSHIBA  (hidden comment: CUS01(TE85L,Q))
D18  USERCOMPTEXT3: TOSHIBA  (hidden comment: CUS01(TE85L,Q))
D19  USERCOMPTEXT3: TOSHIBA  (hidden comment: CUS01(TE85L,Q))
DP5  TP  (value not drawn)
DP6  TP  (value not drawn)
DP34  TP  (value not drawn)
DP35  TP  (value not drawn)
DP44  TP  (value not drawn)
DP45  TP  (value not drawn)
IC2  VALUE3: UCC27524DSD  (hidden comment: L27524)
IC3  VALUE3: TPS70933DRVR  (hidden comment: L709XXA)
L2  3.3uH  VALUE3: 74435580330
Q5  USERCOMPTEXT3: TOSHIBA  VALUE3: TPH3R70APL  (hidden comment: MFNAC)
Q6  USERCOMPTEXT3: TOSHIBA  VALUE3: TPH3R70APL  (hidden comment: MFNAC)
Q7  USERCOMPTEXT3: TOSHIBA  VALUE3: TPH3R70APL  (hidden comment: MFNAC)
Q8  USERCOMPTEXT3: TOSHIBA  VALUE3: TPH3R70APL  (hidden comment: MFNAC)
R16  6.8K  VALUE2: 1W  COMPCOMMENT: 6332
R17  6.8K  (value not drawn)
R18  6.8K  (value not drawn)
R19  240K(F)
R20  24K(F)
R21  1K(J)
R22  1K(J)
R24  0  VALUE2: 250mW  COMPCOMMENT: 3216
R25  0  VALUE2: 250mW  COMPCOMMENT: 3216
R26  0  VALUE2: 250mW  COMPCOMMENT: 3216
R27  0  VALUE2: 250mW  COMPCOMMENT: 3216
R28  10K(J)
R29  15(J)  SIZECODESMD: 6332  VALUE2: 1W
R30  0  VALUE2: 250mW  COMPCOMMENT: 3216
R31  0  VALUE2: 250mW  COMPCOMMENT: 3216
R32  0  VALUE2: 250mW  COMPCOMMENT: 3216
R33  0  VALUE2: 250mW  COMPCOMMENT: 3216
R34  10K(J)
R35  15(J)  SIZECODESMD: 6332  VALUE2: 1W
R36  100K  VALUE2: 250mW
R92  750(F)  NOTMOUNT: NOT MOUNT  SIZECODESMD: 3225  VALUE2: 500mW
R93  750(F)  (value not drawn)
R94  750(F)  (value not drawn)
R95  750(F)  (value not drawn)
R96  750(F)  (value not drawn)
U?#3  DATE: 2018-06-05  FUNCTION: PSFB-Synchronous Rectifier & Output  DRAWINGNUMBER: RD024-SCHEMATIC-01  TITLE: 300W Isolated DC-DC Converter  REVISION: 00  SHEETNUMBER: 3/3  (hidden comment: WAKU_DEF100)

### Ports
3V3_Sec, 12Vout, LGND

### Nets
LGND: C11.1 C12.1 C13.1 C14.1 C15.1 C16.1 C17.1 C18.1 C19.1 C20.1 C21.1 C22.1 C23.1 C24.1 C25.1 C26.1 C27.1 CN5.1 DP35.1 DP45.1 IC2.3 IC3.3 IC3.7 Q5.1 Q5.2 Q5.3 Q6.1 Q6.2 Q6.3 Q7.1 Q7.2 Q7.3 Q8.1 Q8.2 Q8.3 R20.1 R28.1 R34.1 R36.1 R92.1 R93.1 R94.1 R95.1 R96.1 ; port LGND
OUTB1: R21.1 ; off-sheet OUTB1
OUTB2: R22.1 ; off-sheet OUTB2
SEC_1: D15.A Q7.5 Q7.6 Q7.7 Q7.8 Q8.5 Q8.6 Q8.7 Q8.8 R35.2 ; off-sheet SEC_1
SEC_2: L2.1 ; off-sheet SEC_2
SEC_3: D14.A Q5.5 Q5.6 Q5.7 Q5.8 Q6.5 Q6.6 Q6.7 Q6.8 R29.2 ; off-sheet SEC_3
SIG28: IC2.4 R22.2
SIG29: IC2.2 R21.2
SIG37: C17.2 R29.1
SIG39: C18.2 R35.1
SIG41: C19.2 D14.C D15.C R16.2 R17.2 R18.2 R36.2
SIG43: C12.2 IC3.4 R19.1 R20.2
SIG85: Q8.4 R32.2 R33.2 R34.2
SIG86: D16.A D17.C DP5.1 IC2.7
SIG87: Q6.4 R26.2 R27.2 R28.2
SIG89: D16.C R25.1 R26.1
SIG90: Q5.4 R24.2 R25.2
SIG91: D17.A R24.1 R27.1
SIG92: D18.A D19.C DP6.1 IC2.5
SIG93: Q7.4 R30.2 R31.2
SIG94: D19.A R30.1 R33.1
SIG95: D18.C R31.1 R32.1
SIG169: C11.2 C14.2 C15.2 C16.2 C20.2 C21.2 C22.2 C23.2 C24.2 C25.2 C26.2 C27.2 CN4.1 DP34.1 DP44.1 IC2.6 IC3.6 L2.2 R16.1 R17.1 R18.1 R19.2 R92.2 R93.2 R94.2 R95.2 R96.2 ; port 12Vout
NetC13_2: C13.2 IC3.1 ; port 3V3_Sec

Not connected (* = marked no-connect by the designer): IC2 1 8 9; IC3 2 5

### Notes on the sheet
- (near R18) x3
- (φ1.524mm)
- 12V output
- 12V output for sense
- x5pcs
- x7pcs
- (near IC2) 4.5V～18V
- 2012
- GND output for sense
- GND output
- (near CN5) (φ1.524mm)

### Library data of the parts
C11 C14 = C: SQ_PART_MODEL: CON_1U; OriginalSymbolOrigin: (2540,7620); VALUE3: GRJ188R71E105KE11#; RATEDVOLTAGE: 25; MAXGCOUNT: 1; TEMPCHARACTERI2: B; OUMEMAKER: MRT 村田製作所; OUMECLASSIFICATION: セラミックコンデンサ; COMP: PRT_34; NOMINALCAPACITA: 1u; ADSCNVFLAG: ON; OUMEMAKERKATAMEI: GRM188B31E105KA75D; ADSCOMPONENTNAME: C_1608; VALUE2: 25V; CAPACITANCETOLE: K; CDMASTERCADCELG: KC0008; ADSMODELNAME: s_GRM188B31E105KA75D
C12 C20 = C: as C5 on sheet 1
C13 = C: SQ_PART_MODEL: CON_2.2U; OriginalSymbolOrigin: (2540,7620); RATEDVOLTAGE: 10; MAXGCOUNT: 1; OUMEMAKER: MRT 村田製作所; OUMECLASSIFICATION: セラミックコンデンサ; COMP: PRT_76; SIZECODESMD: 1005; NOMINALCAPACITA: 2.2u; ADSCNVFLAG: ON; OUMEMAKERKATAMEI: GRM155C71A225KE11D; ADSCOMPONENTNAME: C_1005; VALUE3: C1005X7S1A225K050BC; CAPACITANCETOLE: K; CDMASTERCADCELG: KC0005; ADSMODELNAME: s_GRM155C71A225KE11D
C15 C16 = C: SQ_PART_MODEL: CON_10U; OriginalSymbolOrigin: (2540,7620); RATEDVOLTAGE: 4; MAXGCOUNT: 1; OUMEMAKER: MRT 村田製作所; OUMECLASSIFICATION: セラミックコンデンサ; COMP: PRT_75; NOMINALCAPACITA: 10u; ADSCNVFLAG: ON; OUMEMAKERKATAMEI: GRM21BC70G106ME45L; ADSCOMPONENTNAME: C_2012; VALUE3: GRM21BC71E106KE11#; VALUE2: 25V; CAPACITANCETOLE: M; CDMASTERCADCELG: KC0006; ADSMODELNAME: s_GRM21BC70G106ME45L
C17 C18 = C: OriginalSymbolOrigin: (2540,7620); VALUE3: GRM219R72A471KA01#; COMP: PRT_85
C19 = C: SQ_PART_MODEL: CON_220N; OriginalSymbolOrigin: (2540,7620); RATEDVOLTAGE: 100; MAXGCOUNT: 1; OUMEMAKER: MRT 村田製作所; OUMECLASSIFICATION: セラミックコンデンサ; COMP: PRT_77; NOMINALCAPACITA: 220n; ADSCNVFLAG: ON; OUMEMAKERKATAMEI: GRM21AR72A224KAC5L; ADSCOMPONENTNAME: C_2012; VALUE3: GRM21AR72A224KAC5#; CAPACITANCETOLE: K; ADSMODELNAME: s_GRM21AR72A224KAC5L
C21 = C: SQ_PART_MODEL: CON_22U; OriginalSymbolOrigin: (2540,7620); RATEDVOLTAGE: 25; MAXGCOUNT: 1; OUMEMAKER: MRT 村田製作所; OUMECLASSIFICATION: セラミックコンデンサ; COMP: PRT_74; NOMINALCAPACITA: 22u; ADSCNVFLAG: ON; OUMEMAKERKATAMEI: GRM32ER71E226ME15L; ADSCOMPONENTNAME: C_3225; VALUE3: GRM32ER71E226ME15#; CAPACITANCETOLE: M; CDMASTERCADCELG: KC0180; ADSMODELNAME: s_GRM32ER71E226ME15L
C22-C27 = C: SQ_PART_MODEL: CON_22U; OriginalSymbolOrigin: (2540,7620); RATEDVOLTAGE: 25; MAXGCOUNT: 1; OUMEMAKER: MRT 村田製作所; OUMECLASSIFICATION: セラミックコンデンサ; COMP: PRT_74; SIZECODESMD: 3225; NOMINALCAPACITA: 22u; ADSCNVFLAG: ON; OUMEMAKERKATAMEI: GRM32ER71E226ME15L; ADSCOMPONENTNAME: C_3225; VALUE3: GRM32ER71E226ME15#; VALUE2: 25V; CAPACITANCETOLE: M; CDMASTERCADCELG: KC0180; ADSMODELNAME: s_GRM32ER71E226ME15L
CN4 CN5 = CN1: OriginalSymbolOrigin: (2540,12700); COMP: PRT_86
D14 D15 = D: SAVEAREA0: -225,-91,12804,7836; SAVECOUNT: 3; TIME: 14:49:55; UPDATEUSER: 19870035; UPDATETIME: 14:20:16; OriginalSymbolOrigin: (5080,5080); COMP: PRT_38
D16-D19 = SBD: as D3 on sheet 1
DP5 DP6 DP34 DP35 DP44 DP45 = TP: as DP1 on sheet 1
IC2 = L27524: SAVEAREA0: -18325,-397,56528,38480; SAVECOUNT: 17; TIME: 12:23:18; UPDATEUSER: cae; UPDATETIME: 15:16:57; OriginalSymbolOrigin: (7620,35560); COMP: PRT_87
IC3 = L709XXA: SAVECOUNT: 38; SAVEAREA0: -24553,-450,60279,43610; TIME: 14:46:30; UPDATEUSER: cae; UPDATETIME: 12:49:59; OriginalSymbolOrigin: (7620,40640); COMP: PRT_78
L2 = L: OriginalSymbolOrigin: (2540,5080); COMP: PRT_73
Q5-Q8 = MFNAC: TIME: 18:29:30; UPDATEUSER: 19990028; UPDATETIME: 14:45:16; SAVECOUNT: 26; SAVEAREA0: -10143,-336,37609,28718; OriginalSymbolOrigin: (5080,25400); COMP: PRT_88
R16 = R: OriginalSymbolOrigin: (5080,5080); VALUE3: RK73BW3ATTE682J; COMP: PRT_84
R17 R18 = R: OriginalSymbolOrigin: (5080,5080); VALUE3: RK73BW3ATTE682J; VALUE2: 1W; COMPCOMMENT: 6332; COMP: PRT_84
R19 = R: OriginalSymbolOrigin: (5080,5080); MAXGCOUNT: 1; COMP: PRT_81; SIZECODESMD: 1005; VALUE3: ERJ2RKF2403X; VALUE2: 63mW
R20 = R: OriginalSymbolOrigin: (5080,5080); MAXGCOUNT: 1; COMP: PRT_82; SIZECODESMD: 1005; VALUE3: ERJ2RKF2402X; VALUE2: 63mW
R21 R22 = R: as R44 on sheet 2
R24-R27 R30-R33 = R: as R3 on sheet 1
R28 R34 = R: as R4 on sheet 1
R29 R35 = R: OriginalSymbolOrigin: (5080,5080); COMP: PRT_83; MAXGCOUNT: 1; VALUE3: RK73B3ATTE150J
R36 = R: OriginalSymbolOrigin: (5080,5080); VALUE3: RK73B2ATTD104J; COMP: PRT_80
R92 = R: OriginalSymbolOrigin: (5080,5080); MAXGCOUNT: 1; COMP: PRT_79; VALUE3: RK73H2ETTE7500F
R93-R96 = R: OriginalSymbolOrigin: (5080,5080); NOTMOUNT: NOT MOUNT; MAXGCOUNT: 1; COMP: PRT_79; SIZECODESMD: 3225; VALUE3: RK73H2ETTE7500F; VALUE2: 500mW
U?#3 = WAKU_DEF100: PLOTTIME: HH:MM; SAVEAREA0: -45080,-4508,463680,304612; TIME: 17:17:20; UPDATEUSER: d5009410; UPDATETIME: 14:09:40; SAVECOUNT: 3; OriginalSymbolOrigin: (10160,284480); PAGENUMBER: 02; DESIGNED: TOSHIBA

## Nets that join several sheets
AUX_1: 1 (T2.2), 2 (D23.A D26.C D27.A)
AUX_2: 1 (T2.3), 2 (D22.A D24.A D25.C)
CS: 1 (D1.C), 2 (R44.1 R45.2 R88.2)
LGND: 2 (10 pins), 3 (44 pins)
NetC1_2: 1 (6 pins), 2 (R37.2 R38.2 R39.1)
NetC13_2: 2 (R70.2 R72.2), 3 (C13.2 IC3.1)
OUTB1: 2 (DP20.1 R71.2), 3 (R21.1)
OUTB2: 2 (DP21.1 R73.2), 3 (R22.1)
PN: 1 (19 pins), 2 (38 pins)
SEC_1: 1 (T2.8 T2.9), 3 (10 pins)
SEC_2: 1 (T2.6 T2.7), 3 (L2.1)
SEC_3: 1 (T2.4 T2.5), 3 (10 pins)
SIG13: 1 (D2.A D9.A), 2 (7 pins)
SIG169: 2 (R56.2 R57.2 R59.2), 3 (27 pins)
